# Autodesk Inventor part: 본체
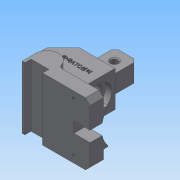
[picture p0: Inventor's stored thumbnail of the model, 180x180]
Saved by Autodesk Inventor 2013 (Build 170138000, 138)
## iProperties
Created: 2016-11
Part Number: 본체
Material: 일반
Document SubType Name: Modeling
Designer: Administrator
Density: 1 g/cm^3
Mass: 170.814 g
Surface Area: 317.29 cm^2
Volume: 170.814 cm^3
Author: Administrator
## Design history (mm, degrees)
sketch "스케치1"
  geometry: L1 (0, 0)-(-58, 0); L2 (-58, 0)-(-58, -30); L3 (-58, -30)-(32, -30); L4 (-40, 18)-(0, 18); L5 (0, 18)-(0, 0); L6 (32, -22)-(0, -22); L7 (0, -22)-(0, 0); L8 (32, -30)-(32, -22); L9 (-58, 0)-(-40, 18); L10 (-58, 0)-(13.121, 0)
  constraints: 20 end point, 2 horizontal, 2 parallel, 2 perpendicular
  dimensions: "d0" = 58 distance of L1.start L1.end; "d1" = 30 distance of L1.end L2.end; "d2" = 90 distance of L2.end L3.end; "d8" = 8 distance between parallel lines of L3 L6; "d9" = 45 deg angle of L10 L9; "d10" = 18 distance between parallel lines of L1 L4; "d11" = 58 distance from line of L1.end L5
extrude "돌출1" new body sketch "스케치1" stored distance "d12" = 40; taper "d13" = 0 deg
sketch "스케치2"
  geometry: L1 (32, -27)-(32, -42); L2 (32, -22)-(32, -30) reference; L3 (32, -42)-(-31, -42); L4 (-44, -27)-(-44, -42); L5 (-44, -42)-(-31, -42); L6 (-18, -27)-(32, -27); A1 r 13 centre (-31, -27) between (-18, -27) and (-44, -27); 1 further point
  constraints: 10 end point, 4 perpendicular, 2 point on circle, 1 centre point, 1 collinear, 1 point on line, 1 tangent, 1 vertical alignment
  dimensions: "d14" = 20 distance of L2.start L1.end; "d15" = 63 distance of L1.end L3.end; "d16" = 26 diameter of A1; "d17" = 15 distance from line of L3 A1.centre; "d19" = 15 distance between parallel lines of L3 L6
extrude "돌출2" join sketch "스케치2" distance "d20" = 15; taper "d21" = 0 deg
sketch "스케치3"
  geometry: L1 (-44, -27)-(-44, -42) reference; L2 (-44, -42)-(32, -42) reference; L3 (-41, -35)-(-21, -35); L4 (-21, -35)-(-21, -42); L5 (-21, -42)-(-41, -42); L6 (-41, -42)-(-41, -35); 1 further point
  constraints: 8 end point, 2 parallel, 1 horizontal, 1 perpendicular, 1 point on line
  dimensions: "d22" = 7 distance between parallel lines of L5 L3; "d24" = 20 distance between parallel lines of L6 L4; "d25" = 3 distance between parallel lines of L1 L6
extrude "돌출3" cut sketch "스케치3" stored distance "d26" = 15; taper "d27" = 0 deg
chamfer "모따기1" distance "d28" = 4; stored, may be unused: second distance "d29" = 2, angle "d30" = 45 deg
fillet "모깎기1" dims "d31" = 5
chamfer "모따기2" distance "d32" = 5; stored, may be unused: second distance "d33" = 2, angle "d34" = 45 deg
sketch "스케치4"
  geometry: L1 (76, 0)-(0, 0); L2 (0, 0)-(0, -40); L3 (0, -40)-(76, -40); L4 (76, -40)-(76, 0); 1 further point
  constraints: 8 end point, 2 parallel, 1 horizontal, 1 perpendicular
extrude "돌출4" join sketch "스케치4" distance "d35" = 12; taper "d36" = 0 deg
sketch "스케치5"
  geometry: L1 (0, 0)-(20, 0); L2 (20, 0)-(20, 7); L3 (20, 7)-(0, 7); L4 (0, 7)-(0, 0); 1 further point
  constraints: 8 end point, 2 parallel, 1 horizontal, 1 perpendicular
extrude "돌출5" cut sketch "스케치5" stored distance "d37" = 12; taper "d38" = 0 deg
sketch "스케치6"
  geometry: L1 (40, 40)-(40, 0) reference; L2 (10, 30)-(35, 30); L3 (35, 30)-(35, 10); L4 (35, 10)-(10, 10); L5 (10, 10)-(10, 30); 3 further points
  constraints: 8 end point, 2 midpoint, 2 parallel, 1 horizontal, 1 horizontal alignment, 1 perpendicular
  dimensions: "d39" = 20 distance between parallel lines of L4 L2; "d41" = 5 distance between parallel lines of L1 L3; "d42" = 25 distance between parallel lines of L5 L3
extrude "돌출6" join sketch "스케치6" distance "d43" = 30; taper "d44" = 0 deg
chamfer "모따기3" distance "d45" = 4; stored, may be unused: second distance "d46" = 2, angle "d47" = 45 deg
fillet "모깎기2" dims "d48" = 3
sketch "스케치7"
  geometry: L1 (-4, -4)-(0, 0) reference; L2 (-4, -27)-(-4, -4) reference; L3 (24, -30)-(-7, -30) reference; L4 (21, -27)-(21, -4) reference; L5 (17, 0)-(21, -4) reference; L6 (0, 0)-(17, 0) reference; C1 r 4 at (8.5, -14.684); A1 r 3 centre (-7, -27) between (-7, -30) and (-4, -27) reference; A2 r 3 centre (24, -27) between (21, -27) and (24, -30) reference; 1 further point
  constraints: 1 centre point
  dimensions: "d49" = 8 diameter of C1; "d50" = 12.5 distance from line of C1.centre L2
sketch "스케치8"
  geometry: L1 (40, -26)-(0, -26) reference; L2 (0, -30)-(40, -30) reference; C1 r 10 at (20, 0); 2 further points
  constraints: 1 centre point, 1 midpoint, 1 vertical alignment
  dimensions: "d51" = 20 diameter of C1; "d52" = 30 distance from line of L2 C1.centre
extrude "돌출7" cut sketch "스케치8" stored distance "d53" = 30; taper "d54" = 0 deg
sketch "스케치9"
  geometry: C1 r 10 at (20, 22) reference; C2 r 14.5 at (20, 22)
  constraints: 1 centre point, 1 coincident
  dimensions: "d55" = 29 diameter of C2
extrude "돌출8" cut sketch "스케치9" distance "d56" = 7; taper "d57" = 0 deg
chamfer "모따기4" distance "d58" = 1; stored, may be unused: second distance "d59" = 2, angle "d60" = 45 deg
sketch "스케치10"
  geometry: L1 (-4, -27)-(-4, -4) reference; L2 (5, -90)-(53, -90) reference; C1 r 4 at (8.5, -13); 1 further point
  constraints: 1 centre point
  dimensions: "d61" = 8 diameter of C1; "d62" = 12.5 distance from line of C1.centre L1; "d63" = 77 distance from line of L2 C1.centre
extrude "돌출9" cut sketch "스케치10" stored distance "d64" = 7; taper "d65" = 0 deg
chamfer "모따기5" distance "d66" = 1; stored, may be unused: second distance "d67" = 2, angle "d68" = 45 deg
fillet "모깎기3" dims "d69" = 3
sketch "스케치11"
  geometry: C1 r 29 at (20, 22); 1 further point
  constraints: 1 centre point, 1 coincident
  dimensions: "d70" = 58 diameter of C1
extrude "돌출10" cut sketch "스케치11" distance "d71" = 18; taper "d72" = 0 deg
sketch "스케치12"
  geometry: L1 (50, -15)-(-10, -15) reference; L2 (26, -15)-(14, -15); L3 (14, -15)-(14, 10); L4 (14, 10)-(26, 10); L5 (26, 10)-(26, -15); 2 further points
  constraints: 8 end point, 3 midpoint, 2 parallel, 1 coincident, 1 horizontal, 1 perpendicular
  dimensions: "d73" = 12 distance between parallel lines of L5 L3; "d75" = 25 distance between parallel lines of L2 L4
extrude "돌출11" cut sketch "스케치12" distance "d76" = 18; taper "d77" = 0 deg
node "작업 평면1"
sketch "스케치13"
  geometry: L1 (45.708, 0)-(45.708, -10) reference; L2 (40.708, -15)-(40.708, 20); 2 further points
  constraints: 2 end point, 1 parallel
  dimensions: "d79" = 18 distance from line of L1 point (27.708, -7.5); "d80" = 35 distance of L2.start L2.end; "d81" = 27.5 vertical distance of L2.end point (27.708, -7.5)
hole "구멍1" sketch "스케치13" at (27.708, -7.5) diameter "d82" = 3.242; stored, may be unused: countersink angle "d86" = 90 deg, drill point angle "d88" = 118 deg; dims "d83" = 49, "d84" = 4, "d85" = 2, "d87" = 50
sketch "스케치14"
  geometry: L1 (0, -19)-(0, 18) reference; L2 (0, 18)-(-40, 18) reference; 2 further points
  constraints: 1 other
  dimensions: "d89" = 25 distance from line of L1 point (-25, 0); "d90" = 18 distance from line of point (-25, 0) L2
feature "엠보싱1" sketch "스케치14" dims "d0" = 58, "d1" = 30, "d2" = 90, "d8" = 8, "d9" = 45 deg, "d10" = 18, "d11" = 58, "d14" = 20, "d15" = 63, "d16" = 26, "d17" = 15, "d19" = 15, "d91" = 0.5, "d92" = 0
node "솔리드1"
mirror "대칭1"
mirror "대칭2"
other parameters: "d78" = 0
